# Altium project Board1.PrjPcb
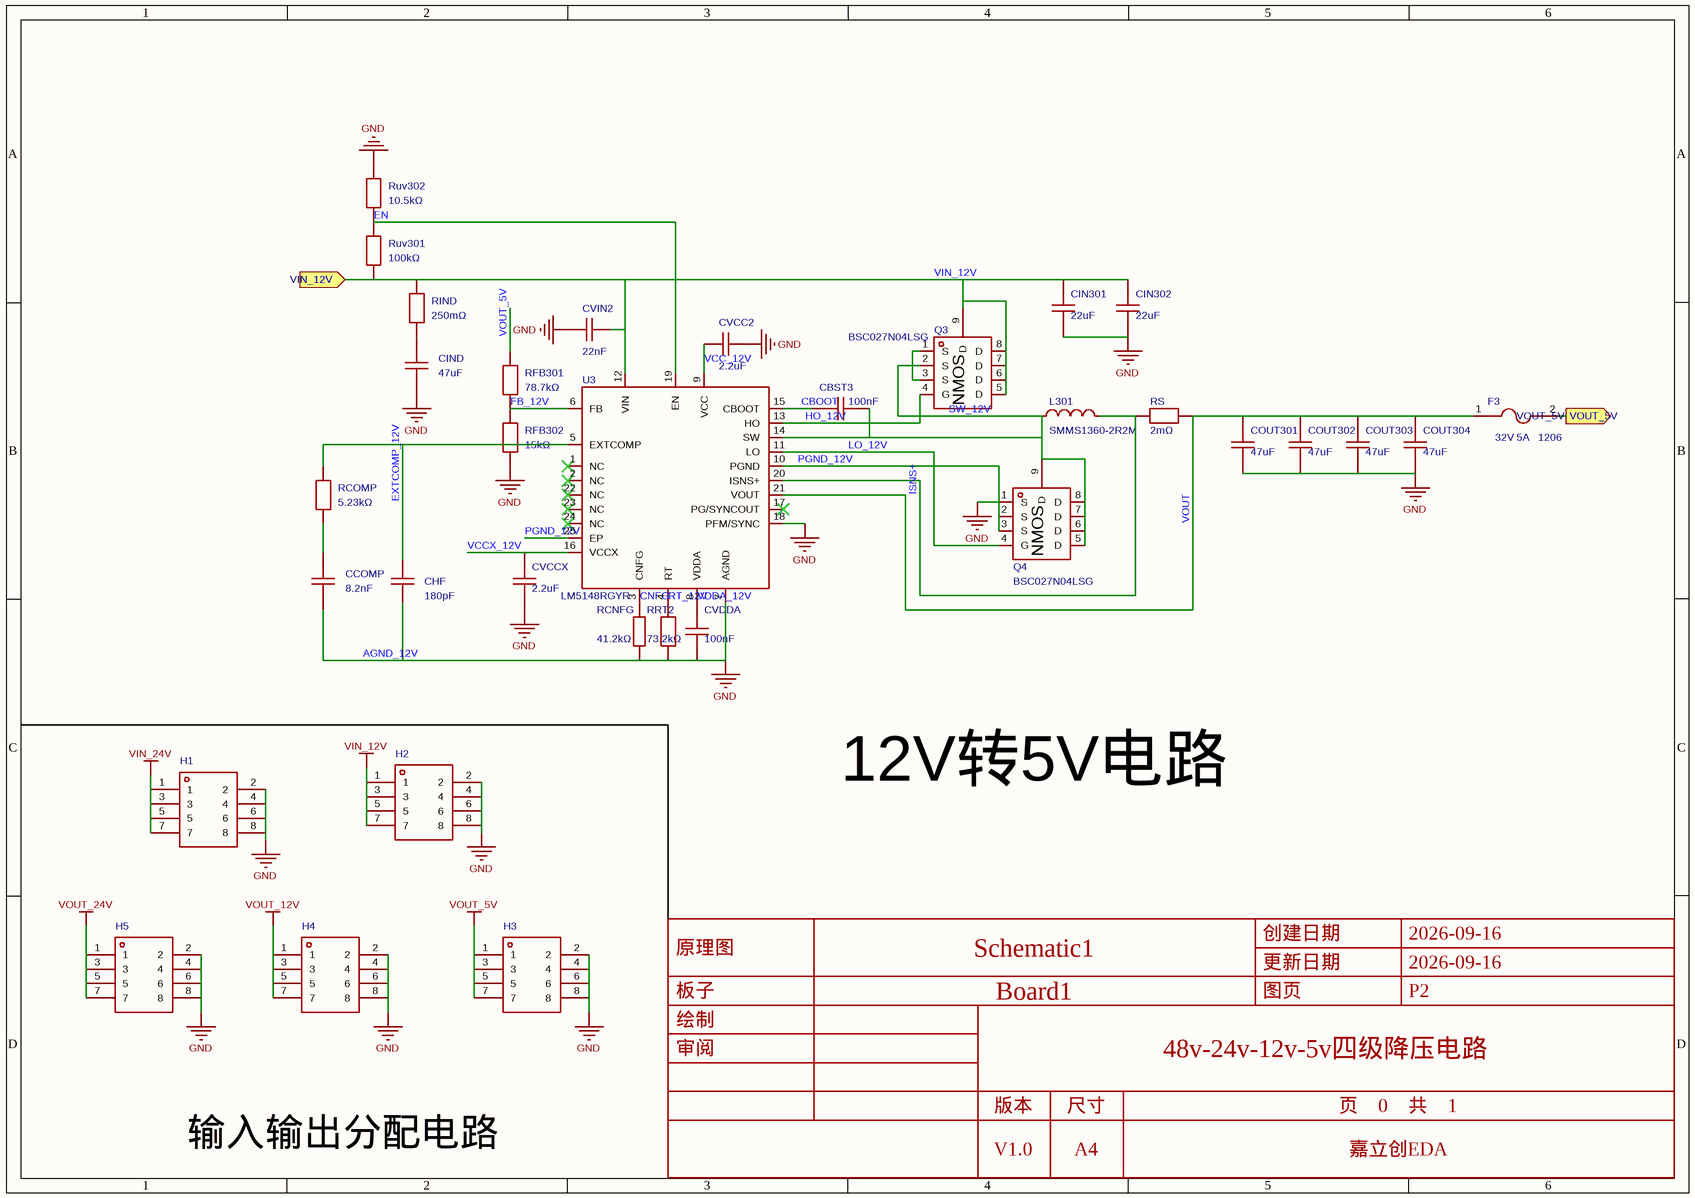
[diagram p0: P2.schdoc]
2 sheets, 82 parts. Net scope: flat (ports and power ports of the same name join across sheets).
Board file: PCB1.pcbdoc
Sheets:
  P2.schdoc
  P1.schdoc

## Sheet P2.schdoc
size 297 x 209 mm; Symbol: Drawing-Symbol_A4; Company: 嘉立创EDA; Version: V1.0; Page Size: A4; @Project Name: 48v-24v-12v-5v四级降压电路; @Update Date: 2026-09-16; @Create Date: 2026-09-16; Device: Drawing-Symbol_A4; @Board Name: Board1; @Page Name: P2; @Create Time: 22:36:17; @Page Count: 1; @Page No: 0; @Schematic Name: Schematic1; @Update Time: 22:36:17; @Assembly Variant: Basic; Border: 1; Title Block Position: 3; Size: A4; Width: 1170; Height: 825; Region Start: 1; X Region Count: 6; Y Region Count: 4; Blade Width: 10

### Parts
CBST3  100nF  [C0805]
CCOMP  8.2nF  [C0603]
CHF  180pF  [C0603]
CIN301  22uF  [C1210]
CIN302  22uF  [C1210]
CIND  47uF  [C1206]
COUT301  47uF  [C1210]
COUT302  47uF  [C1210]
COUT303  47uF  [C1210]
COUT304  47uF  [C1210]
CVCC2  2.2uF  [C0603]
CVCCX  2.2uF  [C0603]
CVDDA  100nF  [C0603]
CVIN2  22nF  [C0603]
F3  Supplier Footprint: 1206  Current Rating: 5A  Voltage Rating (DC): 32V  [F1206]  (hidden comment: JFC1206-1300FS)
H1  (no value)  [HDR-TH_8P-P2.54-V-M-R2-C4-S2.54]
H2  (no value)  [HDR-TH_8P-P2.54-V-M-R2-C4-S2.54]
H3  (no value)  [HDR-TH_8P-P2.54-V-M-R2-C4-S2.54]
H4  (no value)  [HDR-TH_8P-P2.54-V-M-R2-C4-S2.54]
H5  (no value)  [HDR-TH_8P-P2.54-V-M-R2-C4-S2.54]
L301  SMMS1360-2R2M  [IND-SMD_L13.8-W12.6_SMMS1360]
Q3  BSC027N04LSG  [PG-TDSON-8_L5.0-W6.0-P1.27-LS6.2-BL-EP]
Q4  BSC027N04LSG  [PG-TDSON-8_L5.0-W6.0-P1.27-LS6.2-BL-EP]
RCNFG  41.2kΩ  [R0805]
RCOMP  5.23kΩ  [R0603]
RFB301  78.7kΩ  [R0603]
RFB302  15kΩ  [R0603]
RIND  250mΩ  [R0603]
RRT2  73.2kΩ  [R0805]
RS  2mΩ  [R2512]
Ruv301  100kΩ  [R0603]
Ruv302  10.5kΩ  [R0603]
U3  LM5148RGYR  [VQFN-24_L5.5-W3.5-P0.50-BL-EP-2]

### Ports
VIN_12V (in), VOUT_5V (out)

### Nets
AGND_12V: CCOMP.1 CHF.1 CIN301.1 CIN302.1 CIND.1 COUT301.1 COUT302.1 COUT303.1 COUT304.1 CVCC2.2 CVCCX.1 CVDDA.1 CVIN2.2 H1.2 H1.4 H1.6 H1.8 H2.2 H2.4 H2.6 H2.8 H3.2 H3.4 H3.6 H3.8 H4.2 H4.4 H4.6 H4.8 H5.2 H5.4 H5.6 H5.8 Q4.1(S) Q4.2(S) Q4.3(S) RCNFG.1 RFB302.1 RRT2.1 Ruv302.2 U3.7(AGND) U3.10(PGND) U3.18(PFM/SYNC) U3.25(EP)  [also labelled GND, PGND_12V]
VIN_12V: CIN301.2 CIN302.2 CVIN2.1 H2.1 H2.3 H2.5 H2.7 Q3.5(D) Q3.6(D) Q3.7(D) Q3.8(D) Q3.9(D) RIND.2 Ruv301.1 U3.12(VIN) ; port VIN_12V
VIN_24V: H1.1 H1.3 H1.5 H1.7
VOUT_5V: F3.2 H3.1 H3.3 H3.5 H3.7 RFB301.1 ; port VOUT_5V
VOUT_12V: H4.1 H4.3 H4.5 H4.7
VOUT_24V: H5.1 H5.3 H5.5 H5.7
CBOOT: CBST3.2 U3.15(CBOOT)
CNFG: RCNFG.2 U3.3(CNFG)
EN: Ruv301.2 Ruv302.1 U3.19(EN)
EXTCOMP_12V: CHF.2 RCOMP.2 U3.5(EXTCOMP)
FB_12V: RFB301.2 RFB302.2 U3.6(FB)
HO_12V: Q3.4(G) U3.13(HO)
ISNS+: L301.2 RS.1 U3.20(ISNS+)
LO_12V: Q4.4(G) U3.11(LO)
RT_12V: RRT2.2 U3.4(RT)
SW_12V: CBST3.1 L301.1 Q3.1(S) Q3.2(S) Q3.3(S) Q4.5(D) Q4.6(D) Q4.7(D) Q4.8(D) Q4.9(D) U3.14(SW)
VCC_12V: CVCC2.1 U3.9(VCC)
VCCX_12V: CVCCX.2 U3.16(VCCX)
VDDA_12V: CVDDA.2 U3.8(VDDA)
VOUT: COUT301.2 COUT302.2 COUT303.2 COUT304.2 F3.1 RS.2 U3.21(VOUT)
NetCCOMP_2: CCOMP.2 RCOMP.1
NetCIND_2: CIND.2 RIND.1

Not connected (* = marked no-connect by the designer): U3 1(NC)* 2(NC)* 17(PG/SYNCOUT)* 22(NC)* 23(NC)* 24(NC)*

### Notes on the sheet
- 12V转5V电路
- 输入输出分配电路

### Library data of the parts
CBST3 = FCC0805B104K500DT: 容值:100nF;精度:±10%;额定电压:50V;温度系数:X7R;; Manufacturer: FOJAN(富捷); AddInBom: yes; ModelId: 1ba041120af144c991958decab20d2410819f05c4eef4c71ace90d822a990e87; ModelName: C0805_L2.0-W1.3-H1.3; ModelTransform: 78.74,51.181,0,0,0,0,0,0.0005,0; Tolerance: ±10%; Voltage Rating: 50V; Temperature Coefficient: X7R
CCOMP = GRM1885C1H822JA01D: 容值:8.2nF;精度:±5%;额定电压:50V;温度系数:C0G;; Manufacturer: muRata(村田); AddInBom: yes; ModelId: ac125912035d415993ca9572d50418b10819f05c4eef4c71ace90d822a990e87; ModelName: C0603_L1.6-W0.8-H0.8; ModelTransform: 62.992,31.496,0,0,0,0,0,0,0; Tolerance: ±5%; Voltage Rating: 50V; Temperature Coefficient: C0G
CHF = CC0603JRNPO9BN181: 容值:180pF;精度:±5%;额定电压:50V;温度系数:NP0;; Manufacturer: YAGEO(国巨); AddInBom: yes; ModelId: ac125912035d415993ca9572d50418b10819f05c4eef4c71ace90d822a990e87; ModelName: C0603_L1.6-W0.8-H0.8; ModelTransform: 62.992,31.496,0,0,0,0,0,0,0; Tolerance: ±5%; Voltage Rating: 50V; Temperature Coefficient: NP0
CIN301 CIN302 = CL32B226KAJNNNE: 容值:22uF;精度:±10%;额定电压:25V;温度系数:X7R;; Manufacturer: SAMSUNG(三星); AddInBom: yes; ModelId: 833068e7fe044595a6eec77c561794550819f05c4eef4c71ace90d822a990e87; ModelName: C1210_L3.2-W2.5-H2.5; ModelTransform: 125.984,98.425,0,0,0,0,0,0,0; Tolerance: ±10%; Voltage Rating: 25V; Temperature Coefficient: X7R
CIND = CGA1206X5R476M160NT: 容值:47uF;精度:±20%;额定电压:16V;温度系数:X5R;; Manufacturer: HRE(芯声); AddInBom: yes; ModelId: e4be705b945545a48e666415e3682bd80819f05c4eef4c71ace90d822a990e87; ModelName: C1206_L3.2-W1.6-H1.3; ModelTransform: 125.984,62.992,0,0,0,0,0,0,0; Tolerance: ±20%; Voltage Rating: 16V; Temperature Coefficient: X5R
COUT301-COUT304 = CGA1210X5R476M100RT: 容值:47uF;精度:±20%;额定电压:10V;温度系数:X5R;; Manufacturer: HRE(芯声); AddInBom: yes; ModelId: 833068e7fe044595a6eec77c561794550819f05c4eef4c71ace90d822a990e87; ModelName: C1210_L3.2-W2.5-H2.5; ModelTransform: 125.984,98.425,0,0,0,0,0,0,0; Tolerance: ±20%; Voltage Rating: 10V; Temperature Coefficient: X5R
CVCC2 = CL10B225KP8NNNC: 容值:2.2uF;精度:±10%;额定电压:10V;温度系数:X7R;; Manufacturer: SAMSUNG(三星); AddInBom: yes; ModelId: ac125912035d415993ca9572d50418b10819f05c4eef4c71ace90d822a990e87; ModelName: C0603_L1.6-W0.8-H0.8; ModelTransform: 62.992,31.496,0,0,0,0,0,0,0; Tolerance: ±10%; Voltage Rating: 10V; Temperature Coefficient: X7R
CVCCX = CGA0603X7R104K100JT: 容值:100nF;精度:±10%;额定电压:10V;材质(温度系数):X7R;; Manufacturer: HRE(芯声); AddInBom: yes; ModelId: ac125912035d415993ca9572d50418b10819f05c4eef4c71ace90d822a990e87; ModelName: C0603_L1.6-W0.8-H0.8; ModelTransform: 62.992,31.496,0,0,0,0,0,0,0; Tolerance: ±10%; Voltage Rating: 10V; Temperature Coefficient: X7R
CVDDA = FCC0603B104K500CT: 容值:100nF;精度:±10%;额定电压:50V;温度系数:X7R;; Manufacturer: FOJAN(富捷); AddInBom: yes; ModelId: ac125912035d415993ca9572d50418b10819f05c4eef4c71ace90d822a990e87; ModelName: C0603_L1.6-W0.8-H0.8; ModelTransform: 62.992,31.496,0,0,0,0,0,0,0; Tolerance: ±10%; Voltage Rating: 50V; Temperature Coefficient: X7R
CVIN2 = CC0603KRX7R9BB223: 容值:22nF;精度:±10%;额定电压:50V;温度系数:X7R;; Manufacturer: YAGEO(国巨); AddInBom: yes; ModelId: ac125912035d415993ca9572d50418b10819f05c4eef4c71ace90d822a990e87; ModelName: C0603_L1.6-W0.8-H0.8; ModelTransform: 62.992,31.496,0,0,0,0,0,0,0; Tolerance: ±10%; Voltage Rating: 50V; Temperature Coefficient: X7R
F3 = JFC1206-1300FS: 类型:贴片式保险丝;额定电流:3A;额定电压 (AC):63V;额定电压:63V;分断能力:50A;; Manufacturer: JDTfuse(集电通); AddInBom: yes; ModelId: f1628daad26847a79b887277a2bc85410819f05c4eef4c71ace90d822a990e87; ModelName: F1206_L3.2-W1.7-H0.6; ModelTransform: 125.984,66.929,0,0,0,0,0,0,0; Type: 贴片式保险丝; Voltage Rating (AC): 63V; Melting I2t: 1.39; Interrupt Rating: 50A
H1-H5 = HDR-M_2.54_2x4: Symbol: HDR-M-2.54_2x4; ConvertToPcb: yes; ModelId: 9655140a9899454ea9d6a6732d55fb0e0819f05c4eef4c71ace90d822a990e87; ModelName: HDR-TH_8P-P2.54-M-LI-2X4P; ModelTransform: 399.999,200,0,0,0,0,0,0,-118.11
L301 = SMMS1360-2R2M: SMD,13.8×12.6×6.5mm,温升电流(Irms)：20A,合金一体成型电感,大电流; Manufacturer: SXN(顺翔诺); AddInBom: yes; ModelId: 23d83381eee8421299957c6793a499fc0819f05c4eef4c71ace90d822a990e87; ModelName: IND-SMD_L13.8-W12.6-H7.0; ModelTransform: 543.306,496.062,0,0,0,0,0,0,0
Q3 = BSC027N04LSG: 数量:1个N沟道;漏源电压(Vdss):40V;连续漏极电流(Id):100A;导通电阻(RDS(on)):2.7mΩ@10V;耗散功率(Pd):83W;阈值电压(Vgs(th)):2V;; Manufacturer: Infineon(英飞凌); 3D Model: 22bfc06a0ace4ba49a3bccbaac8e141a0819f05c4eef4c71ace90d822a990e87; 3D Model Transform: 208.661,240.157,0,0,0,0,0.0005,-0.0045,0; Number: 1个N沟道; Drain to Source Voltage: 40V; Current - Continuous Drain(Id): 100A; Pd - Power Dissipation: 83W; Gate Threshold Voltage (Vgs(th)): 2V; Gate Charge(Qg): 85nC@10V; Input Capacitance(Ciss): 6.8nF; Reverse Transfer Capacitance (Crss@Vds): 59pF; Type: N沟道; Output Capacitance(Coss): 1.1nF; Vgs: ±20V; AddInBom: yes; ModelName: PG-TDSON-8_L5.0-W6.0-H1.0-P1.27
Q4 = BSC027N04LSG: 数量:1个N沟道;漏源电压(Vdss):40V;连续漏极电流(Id):100A;导通电阻(RDS(on)):2.7mΩ@10V;耗散功率(Pd):83W;阈值电压(Vgs(th)):2V;; Manufacturer: Infineon(英飞凌); AddInBom: yes; ModelId: 22bfc06a0ace4ba49a3bccbaac8e141a0819f05c4eef4c71ace90d822a990e87; ModelName: PG-TDSON-8_L5.0-W6.0-H1.0-P1.27; ModelTransform: 208.661,240.157,0,0,0,0,0.0005,-0.0045,0; Number: 1个N沟道; Drain to Source Voltage: 40V; Current - Continuous Drain(Id): 100A; Pd - Power Dissipation: 83W; Gate Threshold Voltage (Vgs(th)): 2V; Gate Charge(Qg): 85nC@10V; Input Capacitance(Ciss): 6.8nF; Reverse Transfer Capacitance (Crss@Vds): 59pF; Type: N沟道; Output Capacitance(Coss): 1.1nF; Vgs: ±20V
RCNFG = RS-05K2492FT: 电阻类型:厚膜电阻;阻值:24.9kΩ;精度:±1%;功率:125mW;工作电压:150V;温度系数:±100ppm/℃;; Manufacturer: FH(风华); AddInBom: yes; ModelId: 37a81e68749a4138bd2dfa6897b24b850819f05c4eef4c71ace90d822a990e87; ModelName: R0805_L2.0-W1.3-H0.6; ModelTransform: 78.74,51.181,0,0,0,0,0,-0.0005,0; Tolerance: ±1%; Power(Watts): 125mW; Voltage-Supply(Max): 150V
RCOMP = FRC0603F5231TS: 电阻类型:厚膜电阻;阻值:5.23kΩ;精度:±1%;功率:100mW;工作电压:75V;温度系数:±100ppm/℃;; Manufacturer: FOJAN(富捷); AddInBom: yes; ModelId: fc143cca1e79419f9cd78b61e9279f080819f05c4eef4c71ace90d822a990e87; ModelTransform: 31.8897,63.7794,0,90,0,0,0,0,0; Tolerance: ±1%; Power(Watts): 100mW; Voltage-Supply(Max): 75V
RFB301 RFB302 = FRC0603F1001TS: 电阻类型:厚膜电阻;阻值:1kΩ;精度:±1%;功率:100mW;工作电压:75V;温度系数:±100ppm/℃;; Manufacturer: FOJAN(富捷); 3D Model: fc143cca1e79419f9cd78b61e9279f080819f05c4eef4c71ace90d822a990e87; 3D Model Transform: 31.8897,63.7794,0,90,0,0,0,0,0; Tolerance: ±1%; Power(Watts): 100mW; Voltage-Supply(Max): 75V; AddInBom: yes
RIND = FRL0603FR250TS: 电阻类型:厚膜电阻;阻值:250mΩ;精度:±1%;功率:100mW;温度系数:±100ppm/℃;; Manufacturer: FOJAN(富捷); AddInBom: yes; ModelId: fc143cca1e79419f9cd78b61e9279f080819f05c4eef4c71ace90d822a990e87; ModelTransform: 31.8897,63.7794,0,90,0,0,0,0,0; Tolerance: ±1%; Power(Watts): 100mW
RRT2 = FRC0805F9531TS: 电阻类型:厚膜电阻;阻值:9.53kΩ;精度:±1%;功率:125mW;工作电压:150V;温度系数:±100ppm/℃;; Manufacturer: FOJAN(富捷); AddInBom: yes; ModelId: 37a81e68749a4138bd2dfa6897b24b850819f05c4eef4c71ace90d822a990e87; ModelName: R0805_L2.0-W1.3-H0.6; ModelTransform: 78.74,51.181,0,0,0,0,0,-0.0005,0; Tolerance: ±1%; Power(Watts): 125mW; Voltage-Supply(Max): 150V
RS = JER2512F3R002: 电阻类型:采样电阻；合金电阻;阻值:2mΩ;精度:±1%;功率:3W;温度系数:±50ppm/℃;安装方式:贴片;; Manufacturer: JIERR(捷而瑞); AddInBom: yes; ModelId: 954b67263d9e4f3582d8de3f8c8464210819f05c4eef4c71ace90d822a990e87; ModelName: R2512_L6.3-W3.2-H0.6; ModelTransform: 248.031,125.984,0,0,0,0,-0.0005,0,0; Tolerance: ±1%; Power(Watts): 3W
Ruv301 Ruv302 = FRC0603F2003TS: 电阻类型:厚膜电阻;阻值:200kΩ;精度:±1%;功率:100mW;工作电压:75V;温度系数:±100ppm/℃;; Manufacturer: FOJAN(富捷); AddInBom: yes; ModelId: fc143cca1e79419f9cd78b61e9279f080819f05c4eef4c71ace90d822a990e87; ModelTransform: 31.8897,63.7794,0,90,0,0,0,0,0; Tolerance: ±1%; Power(Watts): 100mW; Voltage-Supply(Max): 75V
U3 = LM5148RGYR: 功能类型:降压型;输出类型:-;工作电压:3.5V~80V;输出电压:-;输出电流:-;; Manufacturer: TI(德州仪器); AddInBom: yes; ModelId: 45f7e2343b3f4bfaae8460bff90de0e10819f05c4eef4c71ace90d822a990e87; ModelName: VQFN-24_L5.5-W3.5-H1.0-P0.50; ModelTransform: 217.322,138.5824,0,0,0,0,-0.005,0.005,0; Function: 降压型; Frequency - Switching: 2.2MHz; Synchronous Rectifier: 是; Number of Outputs: 1; Topology: 降压式; Switch tube (built-in/external): 外置

## Sheet P1.schdoc
size 297 x 209 mm; Symbol: Drawing-Symbol_A4; Company: 嘉立创EDA; Version: V1.0; Page Size: A4; @Project Name: 48v-24v-12v-5v四级降压电路; @Update Date: 2026-09-16; @Create Date: 2026-09-16; Device: Drawing-Symbol_A4; @Board Name: Board1; @Page Name: P1; @Create Time: 11:02:59; @Page Count: 1; @Page No: 1; @Schematic Name: Schematic1; @Update Time: 11:02:59; @Assembly Variant: Basic; Border: 1; Title Block Position: 3; Size: A4; Width: 1170; Height: 825; Region Start: 1; X Region Count: 6; Y Region Count: 4; Blade Width: 10
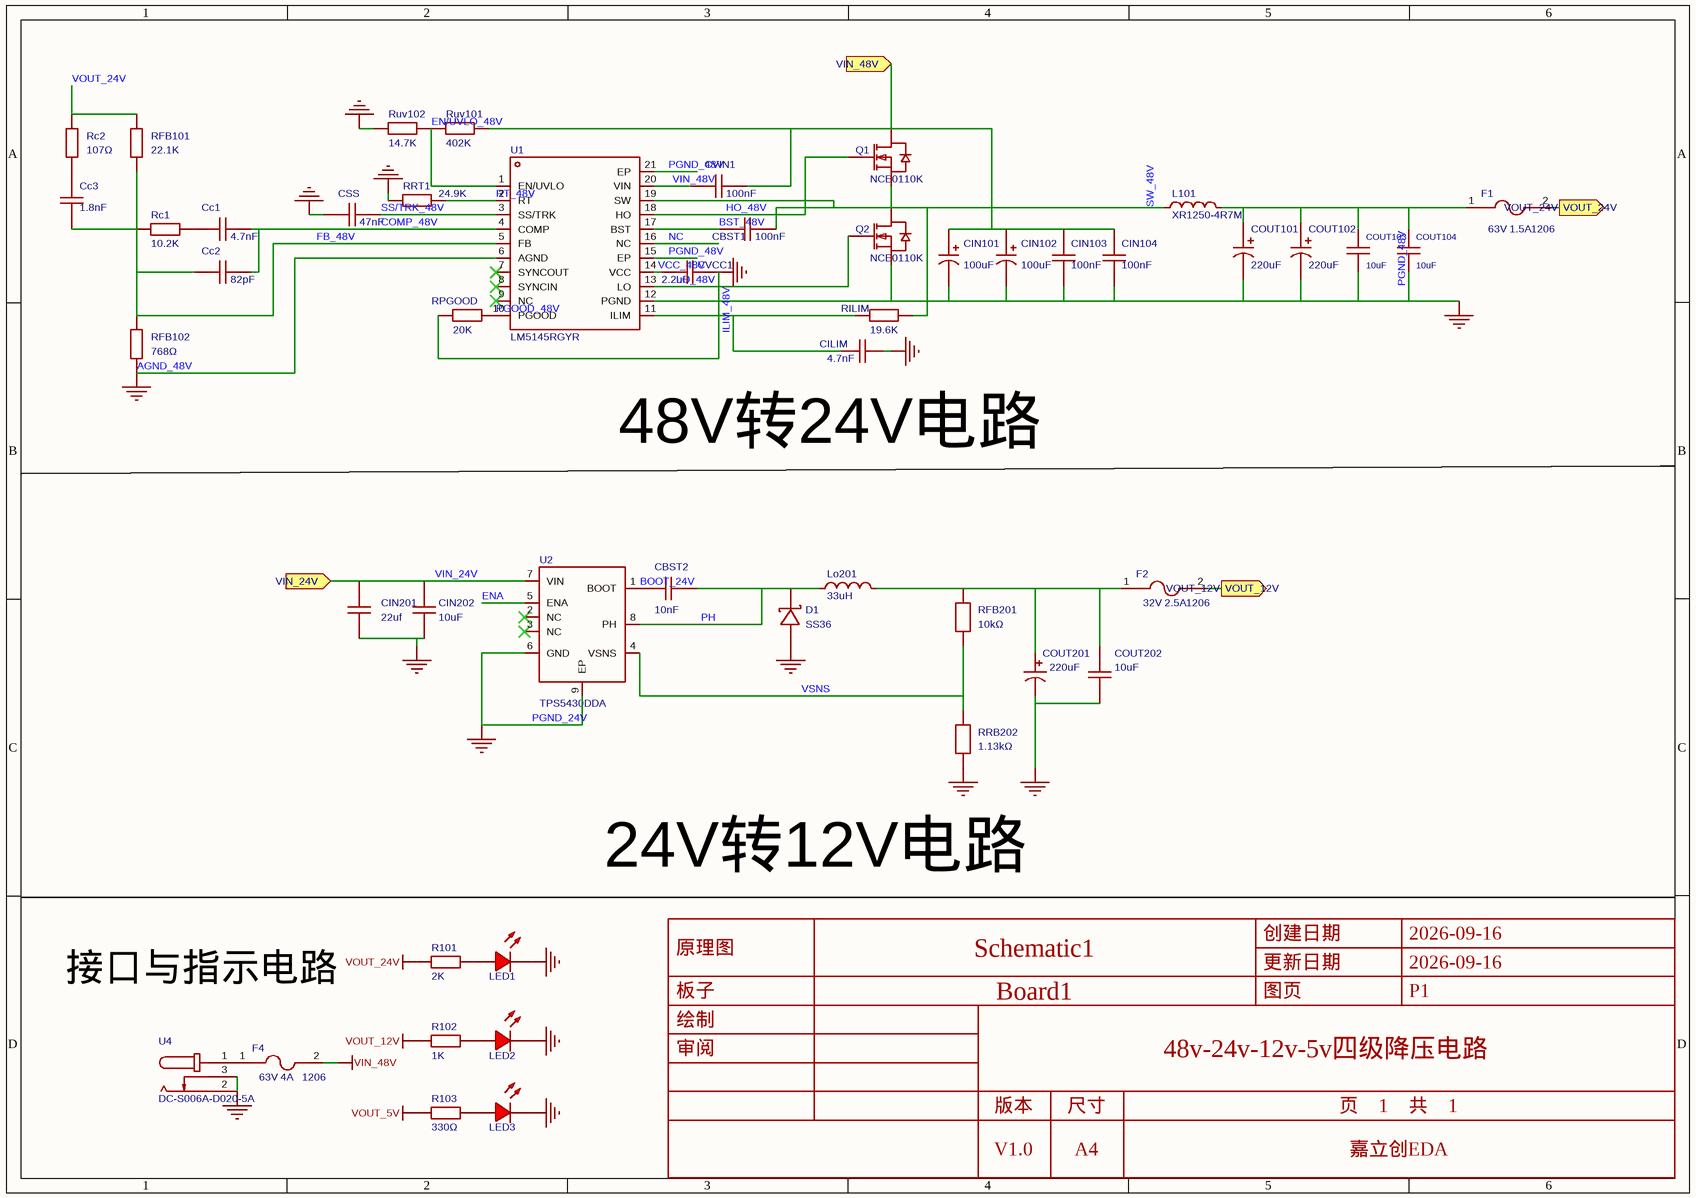
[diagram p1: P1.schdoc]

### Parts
CBST1  100nF  [C0603]
CBST2  10nF  [C0805]
Cc1  4.7nF  [C0603]
Cc2  82pF  [C0603]
Cc3  1.8nF  [C0603]
CILIM  4.7nF  [C0603]
CIN101  100uF  [CAP-SMD_BD12.5-L13.0-W13.0-LS13.7-FD]
CIN102  100uF  [CAP-SMD_BD12.5-L13.0-W13.0-LS13.7-FD]
CIN103  100nF  [C0603]
CIN104  100nF  [C0603]
CIN201  22uf  [C1206]
CIN202  10uF  [C1206]
COUT101  220uF  [CAP-SMD_BD10.0-L10.3-W10.3-LS11.7-FD]
COUT102  220uF  [CAP-SMD_BD10.0-L10.3-W10.3-LS11.7-FD]
COUT103  10uF  [C1206]
COUT104  10uF  [C1206]
COUT201  220uF  [CAP-SMD_BD8.0-L8.3-W8.3-LS9.3-FD-A]
COUT202  10uF  [C0805]
CSS  47nF  [C0603]
CVCC1  2.2uF  [C0603]
CVIN1  100nF  [C0603]
D1  SS36  [SMA_L4.3-W2.6-LS5.2-RD]
F1  Voltage Rating (DC): 63V  Current Rating: 1.5A  Supplier Footprint: 1206  [F1206]  (hidden comment: JFC1206-1300FS)
F2  Supplier Footprint: 1206  Current Rating: 2.5A  Voltage Rating (DC): 32V  [F1206]  (hidden comment: JFC1206-1300FS)
F4  Supplier Footprint: 1206  Current Rating: 4A  Voltage Rating (DC): 63V  [F1206]  (hidden comment: JFC1206-1300FS)
L101  XR1250-4R7M  [IND-SMD_L13.5-W12.6]
LED1  (no value)  [LED-TH_5mm]
LED2  (no value)  [LED-TH_5mm]
LED3  (no value)  [LED-TH_5mm]
Lo201  33uH  [IND-SMD_L8.2-W8.2-LS8.6]
Q1  NCE0110K  [TO-252-2_L6.6-W6.1-P4.57-LS9.9-TL-CW]
Q2  NCE0110K  [TO-252-2_L6.6-W6.1-P4.57-LS9.9-TL-CW]
R101  2K  [R0603]
R102  1K  [R0603]
R103  330Ω  [R0603]
Rc1  10.2K  [R0603]
Rc2  107Ω  [R0603]
RFB101  22.1K  [R0603]
RFB102  768Ω  [R0603]
RFB201  10kΩ  [R0603]
RILIM  19.6K  [R0805]
RPGOOD  20K  [R0603]
RRB202  1.13kΩ  [R0603]
RRT1  24.9K  [R0603]
Ruv101  402K  [R0603]
Ruv102  14.7K  [R0603]
U1  LM5145RGYR  [VQFN-20_L4.5-W3.5-P0.50-BL-EP]
U2  TPS5430DDA  [ESOP-8_L4.9-W3.9-P1.27-LS6.0-BL-EP-2]
U4  DC-S006A-D020-5A  [CONN-TH_DC-S006A-D020-5A]

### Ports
VIN_24V (in), VIN_48V (in), VOUT_12V (out), VOUT_24V (out)

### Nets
AGND_48V: CILIM.2 CIN101.2 CIN102.2 CIN103.1 CIN104.1 CIN201.1 CIN202.1 COUT101.2 COUT102.2 COUT103.1 COUT104.1 COUT201.2 COUT202.1 CSS.1 CVCC1.2 D1.2(A) LED1.2(A) LED2.2(A) LED3.2(A) Q2.3(S) RFB102.2 RPGOOD.1 RRB202.1 RRT1.1 Ruv102.1 U1.6(AGND) U1.12(PGND) U1.15(EP) U1.21(EP) U2.6(GND) U2.9(EP) U4.2 U4.3  [also labelled GND, PGND_24V, PGND_48V]  [project net AGND_12V]
VIN_48V: CVIN1.1 F4.2 U1.20(VIN)
VOUT_5V: R103.1
VOUT_12V: F2.2 R102.1 ; port VOUT_12V
VOUT_24V: F1.2 R101.1 Rc2.2 RFB101.2 ; port VOUT_24V
BOOT_24V: CBST2.1 U2.1(BOOT)
BST_48V: CBST1.1 U1.17(BST)
COMP_48V: Cc1.2 Cc2.2 U1.4(COMP)
EN/UVLO_48V: Ruv101.1 Ruv102.2 U1.1(EN/UVLO)
ENA: U2.5(ENA)
FB_48V: Cc2.1 Cc3.1 Rc1.2 RFB101.1 RFB102.1 U1.5(FB)
HO_48V: Q1.1(G) U1.18(HO)
ILIM_48V: CILIM.1 RILIM.1 U1.11(ILIM)
LO_48V: Q2.1(G) U1.13(LO)
NC: U1.16(NC)
PGOOD_48V: RPGOOD.2 U1.10(PGOOD)
PH: CBST2.2 D1.1(K) Lo201.1 U2.8(PH)
RT_48V: RRT1.2 U1.2(RT)
SS/TRK_48V: CSS.2 U1.3(SS/TRK)
SW_48V: CBST1.2 L101.1 Q1.3(S) Q2.2(D) RILIM.2 U1.19(SW)
VCC_48V: CVCC1.1 U1.14(VCC)
VIN_24V: CIN201.2 CIN202.2 U2.7(VIN) ; port VIN_24V
VSNS: RFB201.1 RRB202.2 U2.4(VSNS)
NetCc1_1: Cc1.1 Rc1.1
NetCc3_2: Cc3.2 Rc2.1
NetCIN101_1: CIN101.1 CIN102.1 CIN103.2 CIN104.2 CVIN1.2 Q1.2(D) Ruv101.2 ; port VIN_48V
NetCOUT101_1: COUT101.1 COUT102.1 COUT103.2 COUT104.2 F1.1 L101.2
NetCOUT201_1: COUT201.1 COUT202.2 F2.1 Lo201.2 RFB201.2
NetF4_1: F4.1 U4.1
NetLED1_1: LED1.1(C) R101.2
NetLED2_1: LED2.1(C) R102.2
NetLED3_1: LED3.1(C) R103.2

Not connected (* = marked no-connect by the designer): U1 7(SYNCOUT)* 8(SYNCIN)* 9(NC)*; U2 2(NC)* 3(NC)*

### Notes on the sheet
- (near CILIM) 48V转24V电路
- 24V转12V电路
- 接口与指示电路

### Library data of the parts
CBST1 CVCC1 = CAP_0603: Symbol: Capacitance; ConvertToPcb: yes; ModelId: ac125912035d415993ca9572d50418b10819f05c4eef4c71ace90d822a990e87; ModelName: C0603_L1.6-W0.8-H0.8; ModelTransform: 62.992,31.496,0,0,0,0,0,0,0
CBST2 = CAP_0805: Symbol: Capacitance; 3D Model: 1ba041120af144c991958decab20d2410819f05c4eef4c71ace90d822a990e87; 3D Model Transform: 78.74,51.181,0,0,0,0,0,0.0005,0; ConvertToPcb: yes; ModelName: C0805_L2.0-W1.3-H1.3
Cc1-Cc3 CSS = CAP_0603: Symbol: Capacitance; 3D Model: ac125912035d415993ca9572d50418b10819f05c4eef4c71ace90d822a990e87; 3D Model Transform: 62.992,31.496,0,0,0,0,0,0,0; ConvertToPcb: yes; ModelName: C0603_L1.6-W0.8-H0.8
CILIM = CC0603JRNPO9BN120: 容值:12pF;精度:±5%;额定电压:50V;温度系数:NP0;; Manufacturer: YAGEO(国巨); AddInBom: yes; ModelId: ac125912035d415993ca9572d50418b10819f05c4eef4c71ace90d822a990e87; ModelName: C0603_L1.6-W0.8-H0.8; ModelTransform: 62.992,31.496,0,0,0,0,0,0,0; Tolerance: ±5%; Voltage Rating: 50V; Temperature Coefficient: NP0
CIN101 CIN102 = JVJ100V100M12X13: 容值:100uF;精度:±20%;额定电压:100V;纹波电流:380mA@120Hz;; Manufacturer: JIERR(捷而瑞); AddInBom: yes; ModelId: 6392bc9430a7457794798829c6f113710819f05c4eef4c71ace90d822a990e87; ModelTransform: 539.369,511.81,0,180,0,0,0,0,0; Tolerance: ±20%; Voltage Rating: 100V; Lifetime: 2000hrs@105℃
CIN103 CIN104 = CC0603KRX7R0BB104: 容值:100nF;精度:±10%;额定电压:100V;温度系数:X7R;; Manufacturer: YAGEO(国巨); AddInBom: yes; ModelId: ac125912035d415993ca9572d50418b10819f05c4eef4c71ace90d822a990e87; ModelName: C0603_L1.6-W0.8-H0.8; ModelTransform: 62.992,31.496,0,0,0,0,0,0,0; Tolerance: ±10%; Voltage Rating: 100V; Temperature Coefficient: X7R
CIN201 CIN202 = CL31Y106KBKVPNE: 容值:10uF;精度:±10%;额定电压:50V;温度系数:X7S;; Manufacturer: SAMSUNG(三星); AddInBom: yes; ModelId: e4be705b945545a48e666415e3682bd80819f05c4eef4c71ace90d822a990e87; ModelName: C1206_L3.2-W1.6-H1.3; ModelTransform: 125.984,62.992,0,0,0,0,0,0,0; Tolerance: ±10%; Voltage Rating: 50V; Temperature Coefficient: X7S
COUT101 COUT102 = JVJ50V220M10x10: 容值:220uF;精度:±20%;额定电压:50V;纹波电流:220mA@120Hz;; Manufacturer: JIERR(捷而瑞); AddInBom: yes; ModelId: 50f22ba8977a4cb2b51f8d950fa665c30819f05c4eef4c71ace90d822a990e87; ModelTransform: 456.692,405.511,0,0,0,0,0,0,0; Tolerance: ±20%; Voltage Rating: 50V; Lifetime: 2000hrs@105℃
COUT103 COUT104 = CL31A106KBHNNNE: 容值:10uF;精度:±10%;额定电压:50V;温度系数:X5R;; Manufacturer: SAMSUNG(三星); AddInBom: yes; ModelId: e4be705b945545a48e666415e3682bd80819f05c4eef4c71ace90d822a990e87; ModelName: C1206_L3.2-W1.6-H1.3; ModelTransform: 125.984,62.992,0,0,0,0,0,0,0; Tolerance: ±10%; Voltage Rating: 50V; Temperature Coefficient: X5R
COUT201 = 35TZV220M8X10.5: 容值:220uF;精度:±20%;额定电压:35V;纹波电流:360mA@120Hz;等效串联电阻(ESR):-;; Manufacturer: Rubycon(红宝石); 3D Model: 557a0f6c1da54cb18f8d6716595fa7ad0819f05c4eef4c71ace90d822a990e87; 3D Model Transform: 354.33,326.771,0,180,0,0,0,0,0; Tolerance: ±20%; Voltage Rating: 35V; Lifetime: 2000hrs@105℃; AddInBom: yes
COUT202 = HGC0805R7106K250NSLJ: 容值:10uF;精度:±10%;额定电压:25V;温度系数:X7R;; Manufacturer: Chinocera(华瓷); AddInBom: yes; ModelId: 1ba041120af144c991958decab20d2410819f05c4eef4c71ace90d822a990e87; ModelName: C0805_L2.0-W1.3-H1.3; ModelTransform: 78.74,51.181,0,0,0,0,0,0.0005,0; Tolerance: ±10%; Voltage Rating: 25V; Temperature Coefficient: X7R
CVIN1 = CL10B104KC8NNNC: 容值:100nF;精度:±10%;额定电压:100V;温度系数:X7R;; Manufacturer: SAMSUNG(三星); AddInBom: yes; ModelId: ac125912035d415993ca9572d50418b10819f05c4eef4c71ace90d822a990e87; ModelName: C0603_L1.6-W0.8-H0.8; ModelTransform: 62.992,31.496,0,0,0,0,0,0,0; Tolerance: ±10%; Voltage Rating: 100V; Temperature Coefficient: X7R
D1 = SS36_C16015: 二极管配置:独立式;正向压降(Vf):700mV@3A;直流反向耐压(Vr):60V;整流电流:3A;; Manufacturer: MDD(辰达半导体); AddInBom: yes; ModelId: e3551acb3c5a4975a5e9d36087fe1fa20819f05c4eef4c71ace90d822a990e87; ModelTransform: 185.039,102.362,0,0,0,0,0,0,0; Diode Configuration: 独立式; Voltage - DC Reverse(Vr): 60V; Current - Rectified: 3A; Reverse Leakage Current (Ir): 500uA@60V; Operating Junction Temperature Range: -55℃~+125℃
F1 F4 = JFC1206-1300FS: 类型:贴片式保险丝;额定电流:3A;额定电压 (AC):63V;额定电压:63V;分断能力:50A;; Manufacturer: JDTfuse(集电通); AddInBom: yes; ModelId: f1628daad26847a79b887277a2bc85410819f05c4eef4c71ace90d822a990e87; ModelName: F1206_L3.2-W1.7-H0.6; ModelTransform: 125.984,66.929,0,0,0,0,0,0,0; Type: 贴片式保险丝; Melting I2t: 1.39; Interrupt Rating: 50A
F2 = JFC1206-1300FS: as F3 on sheet P2
L101 = XR1250-4R7M: 特性：高额定电流。频率高达 3 MHz。最高总温度工作为 125°C。低磁芯损耗。由于模制结构,超低嗡嗡声。无卤且符合 ROHS 标准。应用：笔记本电脑和个人电脑。交换机和服务器。基站。DC/DC 转换器。电池供电设备。SSD 模块; Manufacturer: XR(祥如); AddInBom: yes; ModelId: 987385deb45846018dca7f0b79c9d31d0819f05c4eef4c71ace90d822a990e87; ModelName: IND-SMD_L13.5-W12.6-H5.0; ModelTransform: 529.5265,496.062,0,0,0,0,0,0,0
LED1 = LED_TH-R_5mm: ConvertToPcb: yes; ModelId: fe9cea1bdf7642cd8d9a5077ed0e2b580819f05c4eef4c71ace90d822a990e87; ModelName: LED-TH_BD5.9-P2.54-RD_RED; ModelTransform: 222.16,238.98,581.81,180,0,0,-6,0,-220
LED2 LED3 = LED_TH-R_5mm: 3D Model: fe9cea1bdf7642cd8d9a5077ed0e2b580819f05c4eef4c71ace90d822a990e87; 3D Model Transform: 222.16,238.98,581.81,180,0,0,-6,0,-220; ConvertToPcb: yes; ModelName: LED-TH_BD5.9-P2.54-RD_RED
Lo201 = IHLP3232DZER100M11: 电感值:10uH;精度:±20%;额定电流:5.4A;饱和电流(Isat):6.4A;; Manufacturer: VISHAY(威世); AddInBom: yes; ModelId: c538bf11b7ad499ab79eaf9385e155e10819f05c4eef4c71ace90d822a990e87; ModelTransform: 340.1568,322.44,0,0,0,0,0,0,0; Tolerance: ±20%; Current Rating: 5.4A; Current - Saturation(Isat): 6.4A; DC Resistance(DCR): 51.8mΩ
Q1 Q2 = NCE0110K: 数量:1个N沟道;漏源电压(Vdss):100V;连续漏极电流(Id):9.6A;导通电阻(RDS(on)):140mΩ@10V;耗散功率(Pd):30W;阈值电压(Vgs(th)):2.5V;; Manufacturer: NCE(无锡新洁能); AddInBom: yes; ModelId: ce57f84d66384067af8a68020b6de06d0819f05c4eef4c71ace90d822a990e87; ModelName: TO-252-2L-3P_L6.6-W6.1-H2.3-LS10.1-P4.6; ModelTransform: 259.842,390.52442,0,270,0,0,38.027,-0.598,0; Number: 1个N沟道; Drain to Source Voltage: 100V; Current - Continuous Drain(Id): 9.6A; Pd - Power Dissipation: 30W; Gate Threshold Voltage (Vgs(th)): 2.5V; Gate Charge(Qg): 15.5nC; Input Capacitance(Ciss): 690pF; Reverse Transfer Capacitance (Crss@Vds): 90pF; Type: N沟道; Output Capacitance(Coss): 120pF; Vgs: ±20V
R101 RRT1 = Res_0603: Symbol: 电阻; ConvertToPcb: yes; ModelId: fc143cca1e79419f9cd78b61e9279f080819f05c4eef4c71ace90d822a990e87; ModelTransform: 31.8897,63.7794,0,90,0,0,0,0,0
R102 R103 Rc1 Rc2 RFB101 RFB102 RPGOOD Ruv101 Ruv102 = Res_0603: Symbol: 电阻; 3D Model: fc143cca1e79419f9cd78b61e9279f080819f05c4eef4c71ace90d822a990e87; 3D Model Transform: 31.8897,63.7794,0,90,0,0,0,0,0; ConvertToPcb: yes
RFB201 RRB202 = FRC0603F1001TS: 电阻类型:厚膜电阻;阻值:1kΩ;精度:±1%;功率:100mW;工作电压:75V;温度系数:±100ppm/℃;; Manufacturer: FOJAN(富捷); AddInBom: yes; ModelId: fc143cca1e79419f9cd78b61e9279f080819f05c4eef4c71ace90d822a990e87; ModelTransform: 31.8897,63.7794,0,90,0,0,0,0,0; Tolerance: ±1%; Power(Watts): 100mW; Voltage-Supply(Max): 75V
RILIM = Res_0805: Symbol: 电阻; 3D Model: 37a81e68749a4138bd2dfa6897b24b850819f05c4eef4c71ace90d822a990e87; 3D Model Transform: 78.74,51.181,0,0,0,0,0,-0.0005,0; ConvertToPcb: yes; ModelName: R0805_L2.0-W1.3-H0.6
U1 = LM5145RGYR: 功能类型:降压型;工作电压:6V~75V;输出电压:800mV~60V;输出电流:-;输出类型:可调;; Manufacturer: TI(德州仪器); AddInBom: yes; ModelId: 1552b4df8c4f41af8431dd9c7cd873a30819f05c4eef4c71ace90d822a990e87; ModelName: VQFN-20_L4.5-W3.5-H1.0-P0.50-BL-EP; ModelTransform: 137.795,177.165,0,90,0,0,0,0,0; Function: 降压型; Voltage - Supply: 6V~75V; Frequency - Switching: 1MHz; Synchronous Rectifier: 是; Number of Outputs: 1; Topology: 降压式; Quiescent Current: 1.8mA; Switch tube (built-in/external): 外置; Output Type: 可调
U2 = TPS5430DDA: 功能类型:降压型;工作电压:5.5V~36V;输出电压:1.221V~32.04V;输出电流:3A;输出类型:可调;; Manufacturer: TI(德州仪器); AddInBom: yes; ModelId: 0078439d9e964752ad4b3f828dcb56640819f05c4eef4c71ace90d822a990e87; ModelTransform: 192.913,236.22,0,0,0,0,0,0,0; Function: 降压型; Output Current: 3A; Frequency - Switching: 500kHz; Synchronous Rectifier: 否; Number of Outputs: 1; Topology: 降压式; Quiescent Current: 4.4mA; Switch tube (built-in/external): 内置; Output Type: 可调
U4 = DC-S006A-D020-5A: 连接器类型:DC电源插座;安装方式:弯插;触点内径:2mm;触点外径:6.4mm;额定电流:5A;额定电压:60V;工作温度:-40℃~+85℃;; Manufacturer: G-Switch(品赞); AddInBom: yes; Connector Type: DC电源插座; Inside Contact Diameter: 2mm; Outside Contact Diameter: 6.4mm; Current Rating: 5A; Voltage Rating (Max): 60V

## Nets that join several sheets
AGND_12V: P2 (44 pins), P1 (33 pins)
VOUT_5V: P2 (6 pins), P1 (R103.1)
VOUT_12V: P2 (H4.1 H4.3 H4.5 H4.7), P1 (F2.2 R102.1)
VOUT_24V: P2 (H5.1 H5.3 H5.5 H5.7), P1 (F1.2 R101.1 Rc2.2 RFB101.2)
